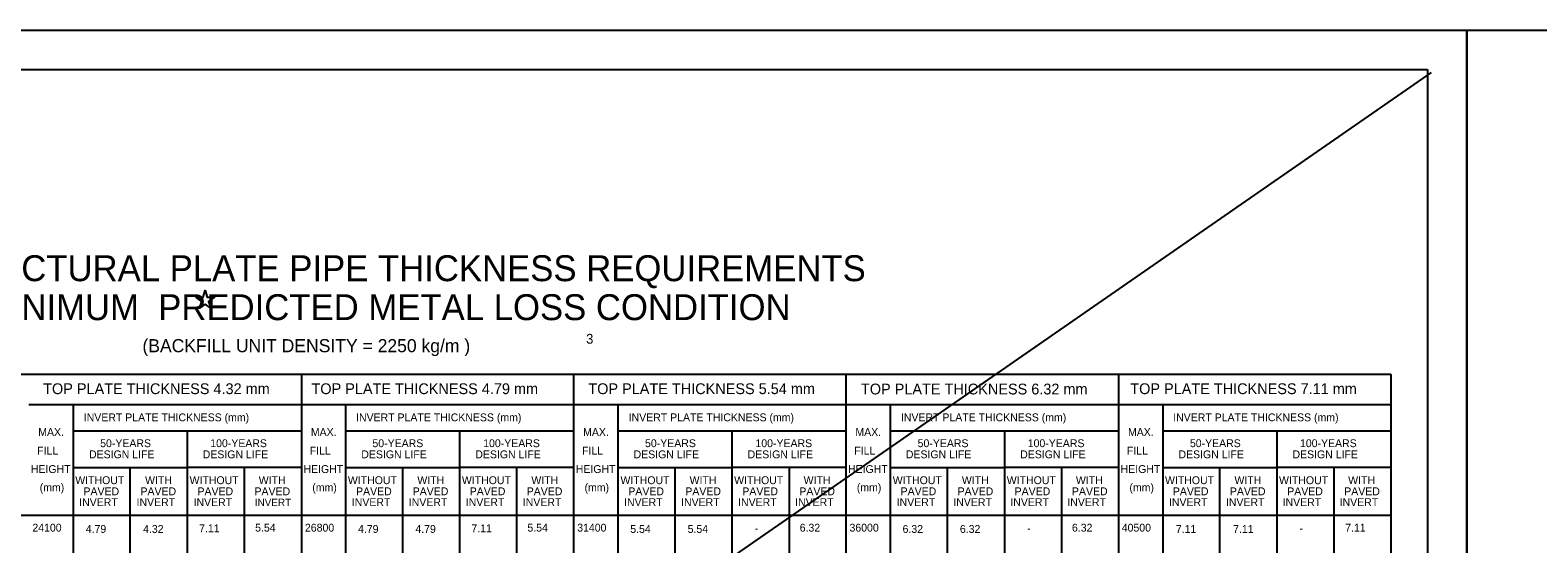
# Model space of a CAD drawing. Extents: x 591 to 2288, y -189 to 2187.
# Drawn here: x 884 to 1459, y 1991 to 2187 of the extents above; entities that cross this region are included whole.
import ezdxf

# ---------------------------------------------------------------- set-up
doc = ezdxf.new("R2010")
doc.units = 0
for name, color, linetype in [('1', 7, 'Continuous'), ('2', 7, 'Continuous'), ('PLT-BNDY', 7, 'Continuous')]:
    doc.layers.add(name, color=color, linetype=linetype)

msp = doc.modelspace()

# ---------------------------------------------------------------- linework, layer by layer
at = {"layer": '1'}
msp.add_line((1418.7, 2171.02), (604.95, 1606.73), dxfattribs=at)
at = {"layer": '2'}
for p, q in [((631.34, 2172.21), (1417.34, 2172.21)), ((1417.34, 2172.21), (1417.34, 1608.21)), ((950.96, 2084.09), (950.96, 2084.09)), ((651.34, 2055.84), (1403.34, 2055.84)), ((987.71, 2055.84), (987.71, 1776.84)), ((1091.59, 2055.84), (1091.59, 1776.84)), ((1195.46, 2055.84), (1195.46, 1776.84)), ((1299.46, 2055.84), (1299.46, 1776.84)), ((1403.34, 2055.84), (1403.34, 1776.84)), ((883.71, 2044.21), (987.71, 2044.21)), ((900.71, 2044.21), (900.71, 1776.84)), ((987.71, 2044.21), (1091.59, 2044.21)), ((1004.59, 2044.21), (1004.59, 1776.84)), ((1091.59, 2044.21), (1195.46, 2044.21)), ((1108.46, 2044.21), (1108.46, 1776.84)), ((1195.46, 2044.21), (1299.46, 2044.21)), ((1212.34, 2044.21), (1212.34, 1776.84)), ((1299.46, 2044.21), (1403.34, 2044.21)), ((1316.34, 2044.21), (1316.34, 1776.84)), ((900.71, 2034.21), (987.71, 2034.21)), ((944.09, 2034.21), (944.09, 1776.84)), ((1004.59, 2034.21), (1091.59, 2034.21)), ((1048.09, 2034.21), (1048.09, 1776.84)), ((1108.46, 2034.21), (1195.46, 2034.21)), ((1151.96, 2034.21), (1151.96, 1776.84)), ((1212.34, 2034.21), (1299.46, 2034.21)), ((1255.96, 2034.21), (1255.96, 1776.84)), ((1316.34, 2034.21), (1403.34, 2034.21)), ((1359.84, 2034.21), (1359.84, 1776.84)), ((900.71, 2020.21), (944.09, 2020.21)), ((922.34, 2020.21), (922.34, 1776.84)), ((987.71, 2020.21), (944.09, 2020.21)), ((965.84, 2020.21), (965.84, 1776.84)), ((1004.59, 2020.21), (1048.09, 2020.21)), ((1026.34, 2020.21), (1026.34, 1776.84)), ((1091.59, 2020.21), (1048.09, 2020.21)), ((1069.84, 2020.21), (1069.84, 1776.84)), ((1108.46, 2020.21), (1151.96, 2020.21)), ((1130.21, 2020.21), (1130.21, 1776.84)), ((1195.46, 2020.21), (1151.96, 2020.21)), ((1173.84, 2020.21), (1173.84, 1776.84)), ((1212.34, 2020.21), (1255.96, 2020.21)), ((1234.09, 2020.21), (1234.09, 1776.84)), ((1299.46, 2020.21), (1255.96, 2020.21)), ((1277.71, 2020.21), (1277.71, 1776.84)), ((1316.34, 2020.21), (1359.84, 2020.21)), ((1337.96, 2020.21), (1337.96, 1776.84)), ((1403.34, 2020.21), (1359.84, 2020.21)), ((1381.59, 2020.21), (1381.59, 1776.84)), ((1403.34, 2001.84), (651.34, 2001.84))]:
    msp.add_line(p, q, dxfattribs=at)
msp.add_lwpolyline([(947.46, 2085.21), (950.21, 2085.21), (950.96, 2087.84), (951.84, 2085.21), (954.59, 2085.21), (952.34, 2083.59), (953.21, 2081.09), (950.96, 2082.59), (948.84, 2081.09), (949.71, 2083.59), (947.46, 2085.21)], dxfattribs=at)
at = {"layer": 'PLT-BNDY'}
for points in [[(591.34, 2187.21), (1432.34, 2187.21), (1432.34, 1593.21), (591.34, 1593.21)], [(1432.34, 2187.21), (2273.34, 2187.21), (2273.34, 1593.21), (1432.34, 1593.21)]]:
    msp.add_lwpolyline(points, close=True, dxfattribs=at)

# ---------------------------------------------------------------- texts
at = {"layer": '2'}
for s, height, p in [('STEEL STRUCTURAL PLATE PIPE THICKNESS REQUIREMENTS', 9.8993, (799.21, 2091.34)), ('WITH MINIMUM  PREDICTED METAL LOSS CONDITION', 9.8993, (828.71, 2076.46)), ('3', 3.75, (1096.34, 2067.46)), ('(BACKFILL UNIT DENSITY = 2250 kg/m )', 5.0003, (927.09, 2064.21)), ('TOP PLATE THICKNESS 4.32 mm', 4.125, (889.21, 2048.21)), ('TOP PLATE THICKNESS 4.79 mm', 4.125, (991.59, 2048.21)), ('TOP PLATE THICKNESS 5.54 mm', 4.125, (1097.21, 2048.21)), ('TOP PLATE THICKNESS 6.32 mm', 4.125, (1201.21, 2048.09)), ('TOP PLATE THICKNESS 7.11 mm', 4.125, (1303.96, 2048.21)), ('INVERT PLATE THICKNESS (mm)', 3, (904.71, 2037.84)), ('INVERT PLATE THICKNESS (mm)', 3, (1008.59, 2037.84)), ('INVERT PLATE THICKNESS (mm)', 3, (1112.59, 2037.84)), ('INVERT PLATE THICKNESS (mm)', 3, (1216.46, 2037.84)), ('INVERT PLATE THICKNESS (mm)', 3, (1320.34, 2037.84)), ('MAX.', 3, (887.34, 2032.22)), ('50-YEARS', 3, (910.96, 2027.96)), ('100-YEARS', 3, (952.96, 2027.96)), ('MAX.', 3, (991.34, 2032.22)), ('50-YEARS', 3, (1014.84, 2027.96)), ('100-YEARS', 3, (1057.09, 2027.96)), ('MAX.', 3, (1095.21, 2032.22)), ('50-YEARS', 3, (1118.84, 2027.96)), ('100-YEARS', 3, (1160.96, 2027.96)), ('MAX.', 3, (1199.09, 2032.22)), ('50-YEARS', 3, (1222.84, 2027.96)), ('100-YEARS', 3, (1264.84, 2027.96)), ('MAX.', 3, (1303.09, 2032.22)), ('50-YEARS', 3, (1326.71, 2027.96)), ('100-YEARS', 3, (1368.71, 2027.96)), ('FILL', 3, (886.92, 2025.09)), ('DESIGN LIFE', 3, (906.71, 2023.71)), ('DESIGN LIFE', 3, (950.09, 2023.71)), ('FILL', 3, (990.92, 2025.09)), ('DESIGN LIFE', 3, (1010.59, 2023.71)), ('DESIGN LIFE', 3, (1054.09, 2023.71)), ('FILL', 3, (1094.79, 2025.09)), ('DESIGN LIFE', 3, (1114.46, 2023.71)), ('DESIGN LIFE', 3, (1157.96, 2023.71)), ('FILL', 3, (1198.67, 2025.09)), ('DESIGN LIFE', 3, (1218.34, 2023.71)), ('DESIGN LIFE', 3, (1261.96, 2023.71)), ('FILL', 3, (1302.67, 2025.09)), ('DESIGN LIFE', 3, (1322.34, 2023.71)), ('DESIGN LIFE', 3, (1365.84, 2023.71)), ('HEIGHT', 3, (884.52, 2018.09)), ('HEIGHT', 3, (988.52, 2018.09)), ('HEIGHT', 3, (1092.4, 2018.09)), ('HEIGHT', 3, (1196.27, 2018.09)), ('HEIGHT', 3, (1300.27, 2018.09)), ('(mm)', 3, (887.89, 2011.09)), ('WITHOUT', 3, (901.46, 2013.84)), ('WITH', 3, (928.09, 2013.84)), ('WITHOUT', 3, (945.09, 2013.84)), ('WITH', 3, (971.46, 2013.84)), ('(mm)', 3, (991.89, 2011.09)), ('WITHOUT', 3, (1005.46, 2013.84)), ('WITH', 3, (1031.96, 2013.84)), ('WITHOUT', 3, (1048.96, 2013.84)), ('WITH', 3, (1075.46, 2013.84)), ('(mm)', 3, (1095.76, 2011.09)), ('WITHOUT', 3, (1109.46, 2013.84)), ('WITH', 3, (1135.84, 2013.84)), ('WITHOUT', 3, (1152.84, 2013.84)), ('WITH', 3, (1179.34, 2013.84)), ('(mm)', 3, (1199.64, 2011.09)), ('WITHOUT', 3, (1213.34, 2013.84)), ('WITH', 3, (1239.71, 2013.84)), ('WITHOUT', 3, (1256.84, 2013.84)), ('WITH', 3, (1283.21, 2013.84)), ('(mm)', 3, (1303.64, 2011.09)), ('WITHOUT', 3, (1317.21, 2013.84)), ('WITH', 3, (1343.71, 2013.84)), ('WITHOUT', 3, (1360.71, 2013.84)), ('WITH', 3, (1387.09, 2013.84)), ('INVERT', 3, (902.96, 2005.46)), ('PAVED', 3, (904.59, 2009.59)), ('INVERT', 3, (924.84, 2005.46)), ('PAVED', 3, (926.34, 2009.59)), ('INVERT', 3, (946.59, 2005.46)), ('PAVED', 3, (948.09, 2009.59)), ('PAVED', 3, (969.84, 2009.59)), ('INVERT', 2.821, (969.96, 2005.46)), ('INVERT', 3, (1006.96, 2005.46)), ('PAVED', 3, (1008.59, 2009.59)), ('INVERT', 3, (1028.71, 2005.46)), ('PAVED', 3, (1030.21, 2009.59)), ('INVERT', 3, (1050.46, 2005.46)), ('PAVED', 3, (1051.96, 2009.59)), ('INVERT', 3, (1072.21, 2005.46)), ('PAVED', 3, (1073.71, 2009.59)), ('INVERT', 3, (1110.84, 2005.46)), ('PAVED', 3, (1112.46, 2009.59)), ('INVERT', 3, (1132.59, 2005.46)), ('PAVED', 3, (1134.21, 2009.59)), ('INVERT', 3, (1154.34, 2005.46)), ('PAVED', 3, (1155.96, 2009.59)), ('INVERT', 3, (1176.09, 2005.46)), ('PAVED', 3, (1177.71, 2009.59)), ('INVERT', 3, (1214.84, 2005.46)), ('PAVED', 3, (1216.34, 2009.59)), ('INVERT', 3, (1236.46, 2005.46)), ('PAVED', 3, (1238.09, 2009.59)), ('INVERT', 3, (1258.21, 2005.46)), ('PAVED', 3, (1259.84, 2009.59)), ('INVERT', 3, (1279.96, 2005.46)), ('PAVED', 3, (1281.71, 2009.59)), ('INVERT', 3, (1318.71, 2005.46)), ('PAVED', 3, (1320.21, 2009.59)), ('INVERT', 3, (1340.46, 2005.46)), ('PAVED', 3, (1341.96, 2009.59)), ('INVERT', 3, (1362.09, 2005.46)), ('PAVED', 3, (1363.84, 2009.59)), ('INVERT', 3, (1383.84, 2005.46)), ('PAVED', 3, (1385.59, 2009.59)), ('24100', 3, (885.09, 1995.71)), ('4.79', 3, (905.46, 1995.21)), ('4.32', 3, (927.34, 1995.21)), ('7.11', 3, (948.71, 1995.46)), ('5.54', 3, (970.09, 1995.71)), ('26800', 3, (989.09, 1995.71)), ('4.79', 3, (1009.34, 1995.21)), ('4.79', 3, (1031.21, 1995.21)), ('7.11', 3, (1052.59, 1995.46)), ('5.54', 3, (1073.96, 1995.71)), ('31400', 3, (1092.96, 1995.71)), ('5.54', 3, (1113.21, 1995.21)), ('5.54', 3, (1135.09, 1995.21)), ('-', 3, (1160.71, 1995.46)), ('6.32', 3, (1177.84, 1995.71)), ('36000', 3, (1196.84, 1995.71)), ('6.32', 3, (1217.09, 1995.21)), ('6.32', 3, (1238.96, 1995.21)), ('-', 3, (1264.59, 1995.46)), ('6.32', 3, (1281.71, 1995.71)), ('40500', 3, (1300.71, 1995.71)), ('7.11', 3, (1321.34, 1995.21)), ('7.11', 3, (1343.21, 1995.21)), ('-', 3, (1368.59, 1995.46)), ('7.11', 3, (1385.96, 1995.71))]:
    msp.add_text(s, height=height, dxfattribs=at).set_placement(p)

doc.saveas('drawing.dxf')
